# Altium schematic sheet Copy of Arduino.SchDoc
size C
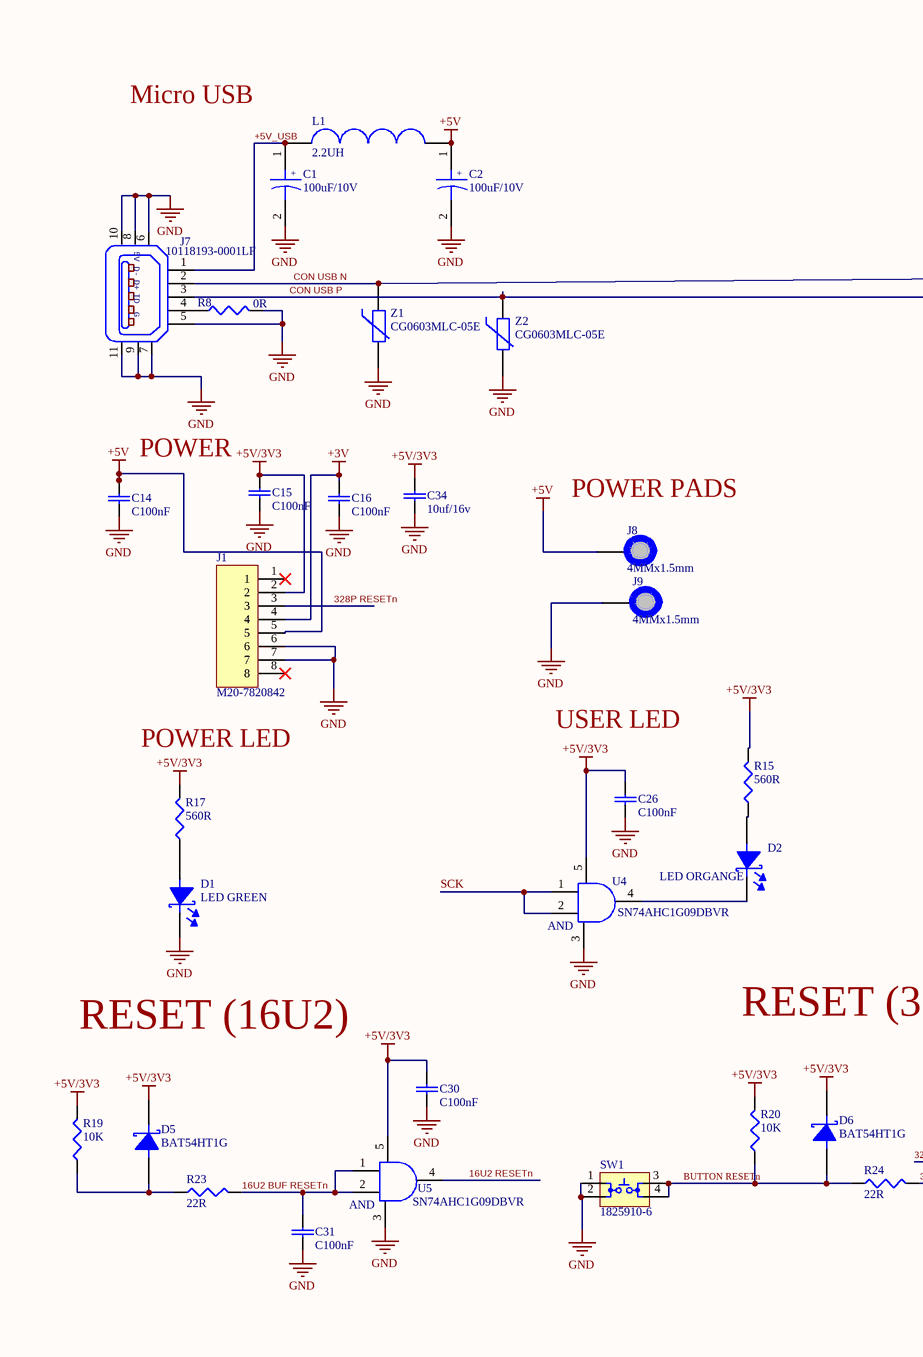
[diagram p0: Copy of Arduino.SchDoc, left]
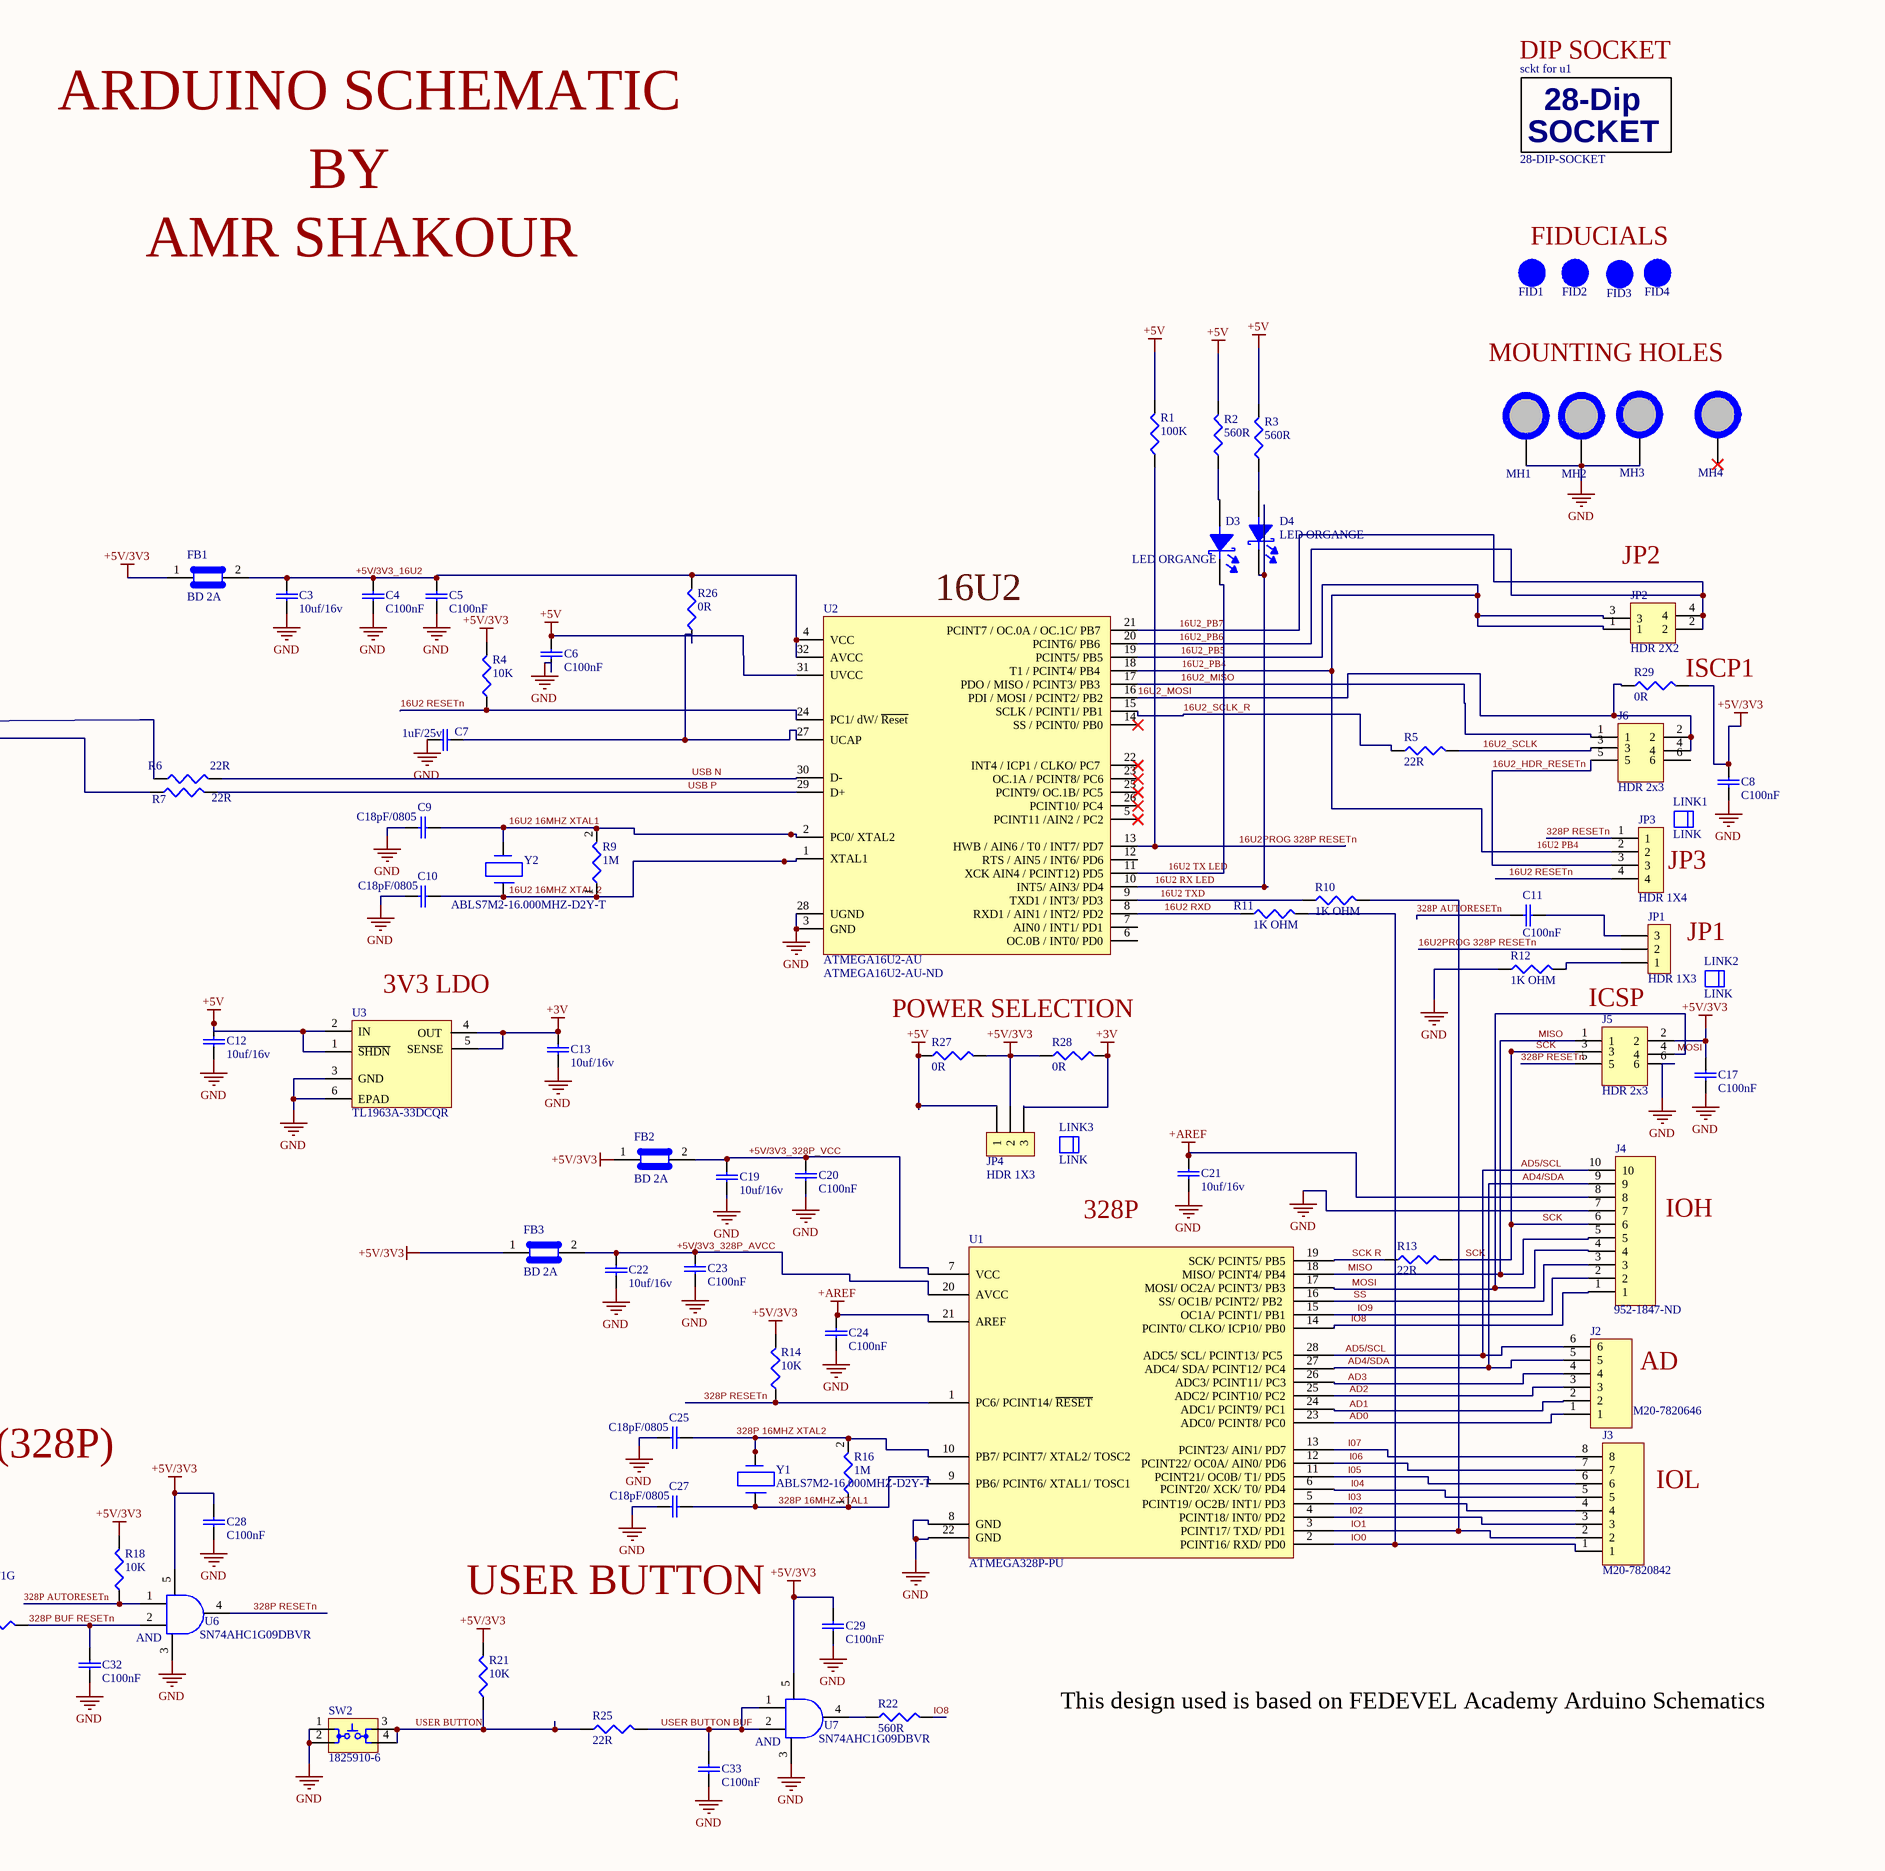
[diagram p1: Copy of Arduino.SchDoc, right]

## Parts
C1  100uF/10V  [c_alu_c_size]
C2  100uF/10V  [c_alu_c_size]
C3  10uf/16v  [C0805/145mm]
C4  C100nF  [c0805/95mm]
C5  C100nF  [c0805/95mm]
C6  C100nF  [c0805/95mm]
C7  1uF/25v  [c0805/95mm]
C8  C100nF  [c0805/95mm]
C9  C18pF/0805  [c0805/95mm]
C10  C18pF/0805  [c0805/95mm]
C11  C100nF  [c0805/95mm]
C12  10uf/16v  [C0805/145mm]
C13  10uf/16v  [C0805/145mm]
C14  C100nF  [c0805/95mm]
C15  C100nF  [c0805/95mm]
C16  C100nF  [c0805/95mm]
C17  C100nF  [c0805/95mm]
C19  10uf/16v  [C0805/145mm]
C20  C100nF  [c0805/95mm]
C21  10uf/16v  [C0805/145mm]
C22  10uf/16v  [C0805/145mm]
C23  C100nF  [c0805/95mm]
C24  C100nF  [c0805/95mm]
C25  C18pF/0805  [c0805/95mm]
C26  C100nF  [c0805/95mm]
C27  C18pF/0805  [c0805/95mm]
C28  C100nF  [c0805/95mm]
C29  C100nF  [c0805/95mm]
C30  C100nF  [c0805/95mm]
C31  C100nF  [c0805/95mm]
C32  C100nF  [c0805/95mm]
C33  C100nF  [c0805/95mm]
C34  10uf/16v  [C0805/145mm]
D1  LED GREEN  [LED 0603]
D2  LED ORGANGE  [LED 0603]
D3  LED ORGANGE  [LED 0603]
D4  LED ORGANGE  [LED 0603]
D5  BAT54HT1G  [SOD323]
D6  BAT54HT1G  [SOD323]
FB1  BD 2A  [c0805/95mm]
FB2  BD 2A  [c0805/95mm]
FB3  BD 2A  [c0805/95mm]
FID1  FID_1MM  [FID_40X120]  (value not drawn)  (no BOM)
FID2  FID_1MM  [FID_40X120]  (value not drawn)  (no BOM)
FID3  FID_1MM  [FID_40X120]  (value not drawn)  (no BOM)
FID4  FID_1MM  [FID_40X120]  (value not drawn)  (no BOM)
J1  M20-7820842  [HDR_FEMAILE_1*8_2.54MM]
J2  M20-7820646  [HDR_FEMAILE_1*6_2.54MM - duplicate]
J3  M20-7820842  [HDR_FEMAILE_1*8_2.54MM]
J4  Supplier Part Number 1: 952-1847-ND  [HDR_FEMAILE_1*10_2.54MM]  (hidden comment: 10-WAY SIL VERT SOCKET L/FREE)
J5  HDR 2x3  [HDR 2x3 2.54mm]
J6  HDR 2x3  [HDR 2x3 2.54mm]
J7  10118193-0001LF  [10118193]
J8  4MMx1.5mm  [PAD_WITH_HOLE_4MMX1.5MM]  (no BOM)
J9  4MMx1.5mm  [PAD_WITH_HOLE_4MMX1.5MM]  (no BOM)
JP1  HDR 1X3  [HDR 1X3_2.54MM]
JP2  HDR 2X2  [HD4 2X2]
JP3  HDR 1X4  [HDR 1X4]
JP4  HDR 1X3  [HDR 1X3_2.54MM]
L1  2.2UH  [C1210_IND]
LINK1  LINK  (mechanical)
LINK2  LINK  (mechanical)
LINK3  LINK  (mechanical)
MH1  mh_7.4mmc3.2  [mh_7.4mmc3.2]  (value not drawn)  (no BOM)
MH2  mh_7.4mmc3.2  [mh_7.4mmc3.2]  (value not drawn)  (no BOM)
MH3  mh_7.4mmc3.2  [mh_7.4mmc3.2]  (value not drawn)  (no BOM)
MH4  mh_7.4mmnc3.2  [mh_7.4mmc3.2 NON COPPER NO PLATTED]  (value not drawn)  (no BOM)
R1  100K  [R0805]
R2  560R  [R0805]
R3  560R  [R0805]
R4  10K  [R0805]
R5  22R  [R0805]
R6  22R  [R0805]
R7  22R  [R0805]
R8  0R  [R0805]
R9  1M  [R0805]
R10  1K OHM  [R0805]
R11  1K OHM  [R0805]
R12  1K OHM  [R0805]
R13  22R  [R0805]
R14  10K  [R0805]
R15  560R  [R0805]
R16  1M  [R0805]
R17  560R  [R0805]
R18  10K  [R0805]
R19  10K  [R0805]
R20  10K  [R0805]
R21  10K  [R0805]
R22  560R  [R0805]
R23  22R  [R0805]
R24  22R  [R0805]
R25  22R  [R0805]
R26  0R  [R0805]
R27  0R  [R0805]
R28  0R  [R0805]
R29  0R  [R0805]
sckt_for_u1  28-DIP-SOCKET  [28_DIP_7.62MM_SOCKET]
SW1  1825910-6  [1825910-6]
SW2  1825910-6  [1825910-6]
U1  ATMEGA328P-PU  [DIP28_pin]
U2  ATMEGA16U2-AU  Supplier Part Number 1: ATMEGA16U2-AU-ND  [ATMEGA16U2-AU]
U3  TL1963A-33DCQR  [DCQ (R-PDSO-G6)]
U4  SN74AHC1G09DBVR  [DBV_SOT_23_5]
U5  SN74AHC1G09DBVR  [DBV_SOT_23_5]
U6  SN74AHC1G09DBVR  [DBV_SOT_23_5]
U7  SN74AHC1G09DBVR  [DBV_SOT_23_5]
Y1  ABLS7M2-16.000MHZ-D2Y-T  [CRYSTAL]
Y2  ABLS7M2-16.000MHZ-D2Y-T  [CRYSTAL]
Z1  CG0603MLC-05E  [R0603]
Z2  CG0603MLC-05E  [R0603]

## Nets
+3V: C13.2(100n) C16.2(100n) J1.4 JP4.3 R28.2 U3.4(OUT) U3.5(SENSE)
+5V: C2.1 C6.2(100n) C12.2(100n) C14.2(100n) J1.5 J8.1 JP4.1 L1.2 R1.2 R2.2 R3.2 R27.1 U2.31(UVCC) U3.1(~{SHDN}) U3.2(IN)
+5V/3V3: C8.2(100n) C15.2(100n) C17.1 C26.2(100n) C28.2(100n) C29.2(100n) C30.2(100n) C34.2(100n) D5.1(Cathode) D6.1(Cathode) FB1.1 FB2.1 FB3.1 J1.2 J5.2 JP4.2 R4.2 R14.2 R15.2 R17.2 R18.2 R19.2 R20.2 R21.2 R27.2 R28.1 R29.2 U4.5(Vcc) U5.5(Vcc) U6.5(Vcc) U7.5(Vcc)
+AREF: C21.2(100n) C24.2(100n) J4.8 U1.21(AREF)
GND: C1.2 C2.2 C3.1 C4.1 C5.1 C6.1 C7.2(100n) C8.1 C9.1 C10.1 C12.1 C13.1 C14.1 C15.1 C16.1 C17.2(100n) C19.2(100n) C20.1 C21.1 C22.2(100n) C23.1 C24.1 C25.1 C26.1 C27.1 C28.1 C29.1 C30.1 C31.1 C32.1 C33.1 C34.1 D1.1(Cathode) J1.6 J1.7 J4.7 J5.6 J7.5 J7.6 J7.7 J7.8 J7.9 J7.10 J7.11 J9.1 MH1.1 MH2.1 MH3.1 R8.2 R12.1 SW1.1 SW1.2 SW2.1 SW2.2 U1.8(GND) U1.22(GND) U2.3(GND) U2.28(UGND) U3.3(GND) U3.6(EPAD) U4.3(GND) U5.3(GND) U6.3(GND) U7.3(GND) Z1.1 Z2.1
16U2 16MHZ XTAL1: C9.2(100n) R9.2 U2.2(PC0/_XTAL2) Y2.2
16U2 16MHZ XTAL 2: C10.2(100n) R9.1 U2.1(XTAL1) Y2.1
16U2 BUF RESETn: C31.2(100n) R23.2 U5.1(A) U5.2(B)
16U2 PB4: JP2.1 JP2.3 JP3.2 U2.18(T1_/_PCINT4/_PB4) U2.19(PCINT5/_PB5)  [also labelled 16U2_PB4, 16U2_PB5]
16U2 RESETn: JP3.4 R4.1 U2.24(PC1/_dW/_~{Reset}) U5.4(Y)
16U2 RX LED: D4.1(Cathode) U2.10(INT5/_AIN3/_PD4)
16U2 RXD: R11.1 U2.8(RXD1_/_AIN1_/_INT2/_PD2)
16U2 TX LED: D3.1(Cathode) U2.11(XCK_AIN4_/_PCINT12)_PD5)
16U2 TXD: R10.1 U2.9(TXD1_/_INT3/_PD3)
16U2_HDR_RESETn: J6.5 JP3.3
16U2_MISO: J6.1 U2.17(PDO_/_MISO_/_PCINT3/_PB3)
16U2_MOSI: J6.2 J6.4 R29.1 U2.16(PDI_/_MOSI_/_PCINT2/_PB2)
16U2_PB6: JP2.2 JP2.4 U2.20(PCINT6/_PB6) U2.21(PCINT7_/_OC.0A_/_OC.1C/_PB7)  [also labelled 16U2_PB7]
16U2_SCLK: J6.3 R5.2
16U2_SCLK_R: R5.1 U2.15(SCLK_/_PCINT1/_PB1)
16U2PROG 328P RESETn: JP1.2 R1.1 U2.13(HWB_/_AIN6_/_T0_/_INT7/_PD7)
328P 16MHZ XTAL1: C27.2(100n) R16.1 U1.9(PB6/_PCINT6/_XTAL1/_TOSC1) Y1.1
328P 16MHZ XTAL2: C25.2(100n) R16.2 U1.10(PB7/_PCINT7/_XTAL2/_TOSC2) Y1.2
328P AUTORESETn: C11.1 R18.1 U6.1(A)
328P BUF RESETn: C32.2(100n) R24.2 U6.2(B)
328P RESETn: J1.3 J5.5 JP3.1 R14.1 U1.1(PC6/_PCINT14/_~{RESET}) U6.4(Y)
+5V/3V3_16U2: C3.2(100n) C4.2(100n) C5.2(100n) FB1.2 R26.2 U2.4(VCC) U2.32(AVCC)
+5V/3V3_328P_AVCC: C22.1 C23.2(100n) FB3.2 U1.20(AVCC)
+5V/3V3_328P_VCC: C19.1 C20.2(100n) FB2.2 U1.7(VCC)
+5V_USB: C1.1 J7.1 L1.1
AD0: J2.1 U1.23(ADC0/_PCINT8/_PC0)
AD1: J2.2 U1.24(ADC1/_PCINT9/_PC1)
AD2: J2.3 U1.25(ADC2/_PCINT10/_PC2)
AD3: J2.4 U1.26(ADC3/_PCINT11/_PC3)
AD4/SDA: J2.5 J4.9 U1.27(ADC4/_SDA/_PCINT12/_PC4)
AD5/SCL: J2.6 J4.10 U1.28(ADC5/_SCL/_PCINT13/_PC5)
BUTTON RESETn: D6.2(Anode) R20.1 R24.1 SW1.3 SW1.4
CON USB N: J7.2 R6.1 Z1.2
CON USB P: J7.3 R7.1 Z2.2
I02: J3.3 U1.4(PCINT18/_INT0/_PD2)
I03: J3.4 U1.5(PCINT19/_OC2B/_INT1/_PD3)
I04: J3.5 U1.6(PCINT20/_XCK/_T0/_PD4)
I05: J3.6 U1.11(PCINT21/_OC0B/_T1/_PD5)
I06: J3.7 U1.12(PCINT22/_OC0A/_AIN0/_PD6)
I07: J3.8 U1.13(PCINT23/_AIN1/_PD7)
IO0: J3.1 R11.2 U1.2(PCINT16/_RXD/_PD0)
IO1: J3.2 R10.2 U1.3(PCINT17/_TXD/_PD1)
IO8: J4.1 R22.2 U1.14(PCINT0/_CLKO/_ICP10/_PB0)
IO9: J4.2 U1.15(OC1A/_PCINT1/_PB1)
MISO: J4.5 J5.1 U1.18(MISO/_PCINT4/_PB4)
MOSI: J4.4 J5.4 U1.17(MOSI/_OC2A/_PCINT3/_PB3)
SCK: J4.6 J5.3 R13.2 U4.1(A) U4.2(B)
SCK R: R13.1 U1.19(SCK/_PCINT5/_PB5)
SS: J4.3 U1.16(SS/_OC1B/_PCINT2/_PB2)
USB N: R6.2 U2.30(D-)
USB P: R7.2 U2.29(D+)
USER BUTTON: R21.1 R25.1 SW2.3 SW2.4
USER BUTTON BUF: C33.2(100n) R25.2 U7.1(A) U7.2(B)
NetC7_1: C7.1 R26.1 U2.27(UCAP)
NetC11_2: C11.2(100n) JP1.3
NetD1_2: D1.2(Anode) R17.1
NetD2_1: D2.1(Cathode) U4.4(Y)
NetD2_2: D2.2(Anode) R15.1
NetD3_2: D3.2(Anode) R2.1
NetD4_2: D4.2(Anode) R3.1
NetD5_2: D5.2(Anode) R19.1 R23.1
NetJ7_4: J7.4 R8.1
NetJP1_1: JP1.1 R12.2
NetR22_1: R22.1 U7.4(Y)

Not connected (* = marked no-connect by the designer): J1 1* 8*; J6 6; MH4 1*; U2 5(PCINT11_/AIN2_/_PC2)* 6(OC.0B_/_INT0/_PD0) 7(AIN0_/_INT1/_PD1) 12(RTS_/_AIN5_/_INT6/_PD6) 14(SS_/_PCINT0/_PB0)* 22(INT4_/_ICP1_/_CLKO/_PC7_)* 23(OC.1A_/_PCINT8/_PC6)* 25(PCINT9/_OC.1B/_PC5)* 26(PCINT10/_PC4)*

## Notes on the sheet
- (near sckt_for_u1) DIP SOCKET
- ARDUINO SCHEMATIC
- BY
- AMR SHAKOUR
- FIDUCIALS
- MOUNTING HOLES
- Micro USB
- (near JP2) JP2
- (near U2) 16U2
- (near R29) ISCP1
- (near C14) POWER
- JP3
- (near J8) POWER PADS
- JP1
- (near U3) 3V3 LDO
- POWER SELECTION
- ICSP
- USER LED
- POWER LED
- 328P
- (near J4) IOH
- AD
- RESET (16U2)
- RESET (328P)
- IOL
- USER BUTTON
- This design used is based on FEDEVEL Academy Arduino Schematics

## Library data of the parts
C1 C2 = EEE-1AA101WR: Cap Aluminum 100uF 10V 20% (5 X 5.4mm) SMD 50mA 1000 hr 85°C T/R; Manufacturer 1: Panasonic; Life (Hours): 1000Hour
C3 C12 C13 C19 C21 C22 C34 = C2012X5R1C106M085AC: CAP CER 10UF 16V X5R 0805; Manufacturer 1: TDK; Dielectric Material: Ceramic; Tolerance: 20%
C4-C6 C8 C11 C14-C17 C20 C23 C24 C26 C28-C33 = C2012X7R1H104K085AA: CAP CER 0.1UF 50V X7R 0805; Manufacturer 1: TDK; Dielectric Material: Ceramic; Capacitance: 100nF; Tolerance: 10%
C7 = C2012X5R1E105K125AA: CAP CER 1UF 25V X5R 0805; Manufacturer 1: TDK; Dielectric Material: Ceramic; Tolerance: 10%
C9 C10 C25 C27 = C0805C180J5GACTU: CAP CER 18PF 50V C0G/NP0 0805; Manufacturer 1: KEMET; Dielectric Material: Ceramic; Tolerance: 5%; Dielectric: C0G; Temperature Coefficient: 30ppm/°C
D1 = LGL29K-F2J1-24-Z: LED Uni-Color Green 572nm 2-Pin Chip 0603(1608Metric) T/R; Manufacturer 1: Osram Opto; Lens Color: White; Forward Current: 20mA; Forward Voltage: 1.7V; Luminous Intensity: 3.5mcd; Viewing Angle: 160°; Lens Style: Flat,Diffused,Colorless,Rectangular; Lens Transparency: Diffused; Test Current: 2mA; Dominant Wavelength: 570nm; Luminous Flux: 0.015lm; Number of LEDs: 1; Lens Size: 0.8mm
D2-D4 = LOL29K-H2K1-24-Z: LED ORANGE DIFFUSED 0603 SMD; Manufacturer 1: Osram Opto; Forward Current: 20mA; Forward Voltage: 1.8V; Luminous Intensity: 6.3mcd; Viewing Angle: 160°; Lens Style: Diffused,Colorless,Rectangular; Test Current: 2mA; Dominant Wavelength: 606nm; Luminous Flux: 0.025lm; Number of LEDs: 1
D5 D6 = BAT54HT1G: DIODE SCHOTTKY 30V 200MA SOD323; Manufacturer 1: ON Semiconductor / Fairchild; Forward Voltage: 800mV; Recovery Time: 5ns; Peak Non-Repetitive Surge Current: 600mA; Element Configuration: Single; Peak Reverse Current: 2uA; Power Dissipation: 200mW; Polarity: Standard; Capacitance: 10pF
FB1-FB3 = MPZ2012S601AT000: Ferrite Beads Multi-Layer Power 600Ohm 25% 100MHz 2A 100mOhm DCR 0805 T/R; Manufacturer 1: TDK; Impedance: 600R; DC Resistance (DCR): 100mR
FID1-FID4 = FID_1MMC: Diducial 40mil diameter, 129mil mask
J1 J3 = M20-7820842: 08-WAY SIL VERT SOCKET L/FREE; Manufacturer 1: Harwin; Number of Contacts: 8; Max Current Rating: 3A; Contact Resistance: 20mR; Connector Type: Receptacle,Socket; Gender: Female; Pitch: 2.54mm
J2 = M20-7820646: 06-WAY SIL VERT SOCKET L/FREE; Manufacturer 1: Harwin; Number of Contacts: 6; Max Current Rating: 3A; Contact Resistance: 20mR; Connector Type: Receptacle,Socket; Gender: Female; Pitch: 2.54mm
J4 = M20-7821046: Manufacturer 1: Harwin; Number of Contacts: 10; Max Current Rating: 3A; Contact Resistance: 20mR; Mating Cycles: 50; Connector Type: Receptacle,Socket; Gender: Receptacle; Insulation Resistance: 1MR; Pitch: 2.54mm; Hole Diameter: 0.8mm
J5 J6 = 67997-106HLF: CONN HEADER VERT 6POS 2.54MM; Manufacturer 1: Amphenol FCI; Number of Contacts: 6; Current Rating: 3A; Voltage Rating: 1.5kV; Insulation Resistance: 5GR; Gender: Male; Connector Type: Male Pin; Row Spacing: 0.1inch; Contact Post Length: 3.05mm
J7 = 10118193-0001LF: CONN RCPT USB2.0 MICRO B SMD R/A; Manufacturer 1: Amphenol FCI; Gender: Female; Connector Type: USB,Receptacle; Number of Contacts: 5; Insulation Resistance: 1GR; Number of Ports: 1; Current Rating: 1.8A; Max Voltage Rating (AC): 100V; Pitch: 0.65mm
J8 J9 = PAD_WITH_HOLE_4MMx1.5MM
JP1 JP4 = 68000-103HLF: CONN HEADER VERT 3POS 2.54MM; Manufacturer 1: Amphenol FCI; Number of Contacts: 3; Current Rating: 3A; Voltage Rating: 1.5kV; Insulation Resistance: 5GR; Gender: Male; Connector Type: Male Pin; Contact Post Length: 2.41mm
JP2 = 68602-104HLF: CONN HEADER 4POS .100 STR 30AU; Manufacturer 1: Amphenol FCI; Number of Contacts: 4; Current Rating: 3A; Voltage Rating: 1.5kV; Insulation Resistance: 5GR; Gender: Male; Connector Type: Male Pin; Pitch: 2.54mm; Row Spacing: 0.1inch; Contact Post Length: 3.81mm
JP3 = 68001-204HLF: CONN HEADER VERT 4POS 2.54MM; Manufacturer 1: Amphenol FCI; Current Rating: 3A; Voltage Rating: 1.5kV; Number of Positions: 4; Insulation Resistance: 5GR; Gender: Male; Connector Type: Male Pin; Contact Post Length: 3.05mm
L1 = L1210R2R2MDWIT: FIXED IND 2.2UH 2A 80 MOHM SMD; Manufacturer 1: KEMET; Core Material: Ferrite; Tolerance: 20%; Shielding: Unshielded; Self Resonant Frequency: 190MHz; DC Resistance (DCR): 80mR; Test Frequency: 100kHz; DC Current: 1.13A
LINK1-LINK3 = QPC02SXGN-RC: CONN JUMPER SHORTING .100" GOLD; Manufacturer 1: Sullins; Number of Positions: 2; Pitch: 0.1inch
MH4 = mh_7.4mmnc3.2: HOLE 7.4MM NON COPPER
R1 = RC0805FR-07100KL: RES SMD 100K OHM 1% 1/8W 0805; Manufacturer 1: Yageo; Resistance: 100kR; Temperature Coefficient: 100ppm/°C; Power Rating: 125mW; Voltage Rating (DC): 150V
R2 R3 R15 R17 R22 = RC0805JR-07560RL: RES SMD 560 OHM 5% 1/8W 0805; Manufacturer 1: Yageo; Temperature Coefficient: 100ppm/°C; Power Rating: 125mW; Voltage Rating: 150V
R4 R14 R18-R21 = RC0805FR-0710KL: RES SMD 10K OHM 1% 1/8W 0805; Manufacturer 1: Yageo; Resistance: 10kR; Temperature Coefficient: 100ppm/°C; Power Rating: 125mW; Voltage Rating: 150V
R5-R7 R13 R23-R25 = RC0805FR-0722RL: RES SMD 22 OHM 1% 1/8W 0805; Manufacturer 1: Yageo; Temperature Coefficient: 100ppm/°C; Power Rating: 125mW; Voltage Rating: 150V
R8 R26-R29 = RC0805JR-070RL: RES SMD 0 OHM JUMPER 1/8W 0805; Manufacturer 1: Yageo; Resistance: 0mR; Tolerance: 5%; Power Rating: 125mW; Voltage Rating: 150V; Temperature Coefficient: 200ppm/°C
R9 R16 = RC0805FR-071ML: RES SMD 1M OHM 1% 1/8W 0805; Manufacturer 1: Yageo Phycomp; Temperature Coefficient: 100ppm/°C; Resistance: 1MR; Power Rating: 125mW; Voltage Rating (DC): 150V
R10-R12 = RC0805FR-071KL: RES SMD 1K OHM 1% 1/8W 0805; Manufacturer 1: Yageo; Resistance: 1kR; Temperature Coefficient: 100ppm/°C; Voltage Rating (DC): 150V; Power Rating: 125mW
sckt_for_u1 = 4828-3004-CP: CONN IC DIP SOCKET 28POS TIN; Manufacturer 1: 3M; Number of Contacts: 28; Gender: Female; Insulation Resistance: 5GR; Connector Type: DIP,Socket; Current Rating: 1A; Pitch: 2.54mm; Row Spacing: 7.62mm
SW1 SW2 = 1825910-6: ALCOSWITCH - TE CONNECTIVITY - 1825910-6 - TACT SWITCH, SPST, 0.05A, 24VDC, SOLDER; Manufacturer 1: TE Connectivity Alcoswitch; Actuator Material: PBT; Mechanical Life: 100000Cycles; Operating Force: 160gf; Illumination Type: Non-Illuminated,Illuminated; Switch Travel: 0.25mm; Switch Function: Off-Mom; Actuator Type: Standard; Max Voltage Rating (DC): 24V; Contact Current Rating: 50mA; Contact Resistance: 100mR; Actuator Length: 0.055inch
U1 = ATMEGA328P-PU: ATMEL         ATMEGA328P-PU            8 Bit Microcontroller, Low Power High Performance, ATmega, 20 MHz, 32 KB, 2 KB, 28 Pins, DIP; Manufacturer 1: Microchip / Atmel; Core Architecture: AVR; RAM Size: 2KB; Number of PWM Channels: 6; Number of Timers/Counters: 3; Min Supply Voltage: 1.8V; Max Supply Voltage: 5.5V; Interface: I2C,SPI,UART,USART,2-Wire; Number of I/Os: 23; Frequency: 20MHz; Oscillator Type: Internal; Data Bus Width: 8b; Number of SPI Channels: 1; Watchdog Timer: Yes; Memory Type: FLASH; Memory Size: 32KB; Peripherals: Brown-out Detect/Reset,POR,PWM,WDT
U2 = ATMEGA16U2-AU: MICROCHIP - ATMEGA16U2-AU - MCU, 8BIT, MEGAAVR, 16MHZ, TQFP-32; Manufacturer 1: Microchip / Atmel; Core Architecture: AVR; Data Bus Width: 8b; RAM Size: 512B; Interface: SPI,UART,USB,USART,Serial; Number of Timers/Counters: 2; Max Supply Voltage: 5.5V; Min Supply Voltage: 2.7V; Number of Programmable I/O: 22; Watchdog Timer: Yes; Memory Type: FLASH; Memory Size: 16KB; Number of PWM Channels: 5; Oscillator Type: Internal; Number of SPI Channels: 1; Peripherals: Brown-out Detect/Reset,POR,PWM,WDT
U3 = TL1963A-33DCQR: IC REG LINEAR 3.3V 1.5A SOT223-6; Manufacturer 1: Texas Instruments; Dropout Voltage: 340mV; Number of Outputs: 1; Max Input Voltage: 20V; Min Input Voltage: 2.1V; Min Current Limit: 1.6A; Input Bias Current: 1mA; Polarity: Positive; Accuracy: 3%; Output Type: Fixed
U4-U7 = SN74AHC1G09DBVR: IC GATE AND 1CH 2-INP SOT23-5; Manufacturer 1: Texas Instruments; Min Supply Voltage: 2V; Max Supply Voltage: 5.5V; Quiescent Current: 1uA; Number of Inputs: 2; Propagation Delay: 7.5ns; Output Current: 25mA; Number of Circuits: 1; Low Level Output Current: 8mA
Y1 Y2 = ABLS7M2-25.000MHZ-D-2Y-T: ABRACON         ABLS7M2-25.000MHZ-D-2Y-T             CRYSTAL, 25MHZ, 18PF, HC-49US; Tolerance: 20ppm; Frequency Stability: 30ppm; ESR (Equivalent Series Resistance): 60R
Z1 Z2 = CG0603MLC-05E: VARISTOR 0603; Manufacturer 1: Bourns; Capacitance: 0.5pF; Voltage Rating (DC): 5V; Number of Channels: 1; Clamping Voltage: 20V; Current Rating: 50nA; Voltage Rating (AC): 8V; Turn-On Delay Time: 1ns; Element Configuration: Single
